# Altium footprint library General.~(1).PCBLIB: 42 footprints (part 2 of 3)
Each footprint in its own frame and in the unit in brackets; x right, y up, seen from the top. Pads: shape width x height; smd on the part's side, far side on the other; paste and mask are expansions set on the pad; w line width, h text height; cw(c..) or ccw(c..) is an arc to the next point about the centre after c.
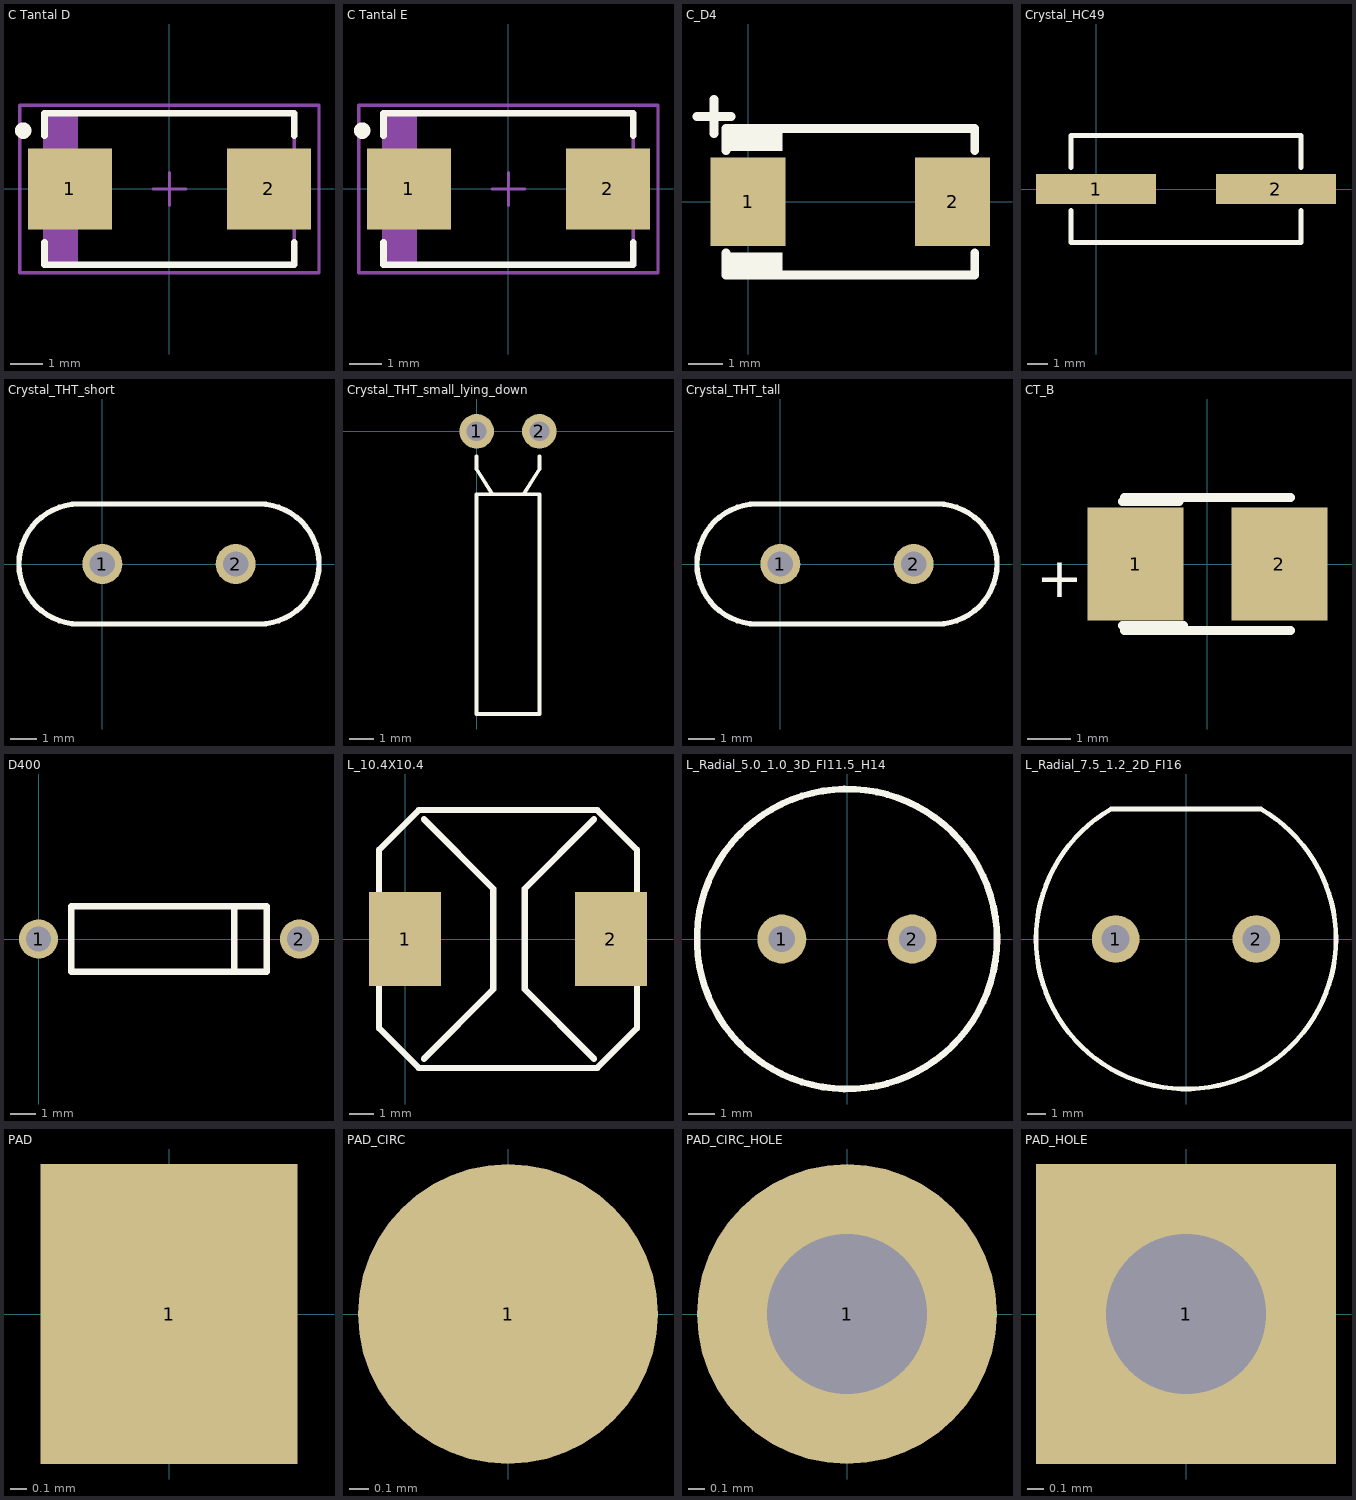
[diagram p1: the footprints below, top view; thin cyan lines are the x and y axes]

## C Tantal D [mm] "Molded Capacitor, 2-Leads, Body 7,3x4,3mm, IPC Medium Density"
height 3.1
pads (2):
  rect 2.55x2.45 smd: 1(-3.025,0) 2(3.025,0)
Top Overlay:
  circle w0.25: c-4.45,1.775 r0.125
  lines w0.2: -3.8,-1.625 -3.8,-2.3 3.8,-2.3 3.8,-1.625 ; -3.8,1.625 -3.8,2.3 3.8,2.3 3.8,1.625
Mechanical 13:
  rectangle: -3.8,-2.3 -2.778,2.3
  lines w0.1: -3.8,-2.3 3.8,-2.3 3.8,2.3 -3.8,2.3 -3.8,-2.3
Mechanical 15:
  lines w0.1: -0.5,0 0.5,0 ; 0,-0.5 0,0.5 ; -4.55,-2.55 4.55,-2.55 4.55,2.55 -4.55,2.55 -4.55,-2.55
3D body "User Library-cap_d.step": height 2.83, standoff 0.02, extent -3.647,-2.159 3.647,2.141

## C Tantal E [mm] "Molded Capacitor, 2-Leads, Body 7,3x4,3mm, IPC Medium Density"
height 4.3
pads (2):
  rect 2.55x2.45 smd: 1(-3.025,0) 2(3.025,0)
Top Overlay:
  circle w0.25: c-4.45,1.775 r0.125
  lines w0.2: -3.8,-1.625 -3.8,-2.3 3.8,-2.3 3.8,-1.625 ; -3.8,1.625 -3.8,2.3 3.8,2.3 3.8,1.625
Mechanical 13:
  rectangle: -3.8,-2.3 -2.778,2.3
  lines w0.1: -3.8,-2.3 3.8,-2.3 3.8,2.3 -3.8,2.3 -3.8,-2.3
Mechanical 15:
  lines w0.1: -0.5,0 0.5,0 ; 0,-0.5 0,0.5 ; -4.55,-2.55 4.55,-2.55 4.55,2.55 -4.55,2.55 -4.55,-2.55
3D body "User Library-cap_e.step": height 4.13, standoff 0.02, extent -3.647,-2.141 3.647,2.159

## C_D4 [mm]
pads (2):
  rect 2.2x2.6 smd: 1(0,0) 2(6,0)
Top Overlay:
  region: -0.625,1.5 1,1.5 1,2.25 -0.625,2.25
  region: -0.625,-2.25 1,-2.25 1,-1.5 -0.625,-1.5
  lines w0.254: -1.5,2.5 -0.5,2.5 ; -1,2 -1,3 ; -0.65,-1.5 -0.65,-2.15 6.65,-2.15 6.65,-1.5 ; -0.65,1.5 -0.65,2.15 6.65,2.15 6.65,1.5

## Crystal_HC49 [mm] "Crystall SMD short HC49"
height 4
pads (2):
  rect 6x1.5 smd: 1(0,0) 2(8.999,0)
Top Overlay:
  lines w0.254: -1.251,-1.079 -1.251,-2.667 10.25,-2.667 10.25,-1.079 ; -1.251,1.079 -1.251,2.667 10.25,2.667 10.25,1.079
3D body "User Library-hc49_cystal.step": height 5.08, standoff 0, extent -2.128,-2.413 11.272,2.487

## Crystal_THT_short [mil] "Crystal short THT"
height 157.48
pads (2):
  round 60 hole 38: 1(0,0) 2(200,0)
Top Overlay:
  lines w8: -35,-90 cw(c-35,0) -35,90 235,90 cw(c235,0) 235,-90 -35,-90
3D body "User Library-HP49US.step": height 138.4, standoff -156.88, extent -123.43,-90 323.43,93.07

## Crystal_THT_small_lying_down [mm]
pads (2):
  round 1.4 hole 0.8: 1(0,0) 2(2.54,0)
Top Overlay:
  lines w0.15: 0,-1.016 0,-1.524 0.635,-2.54 ; 1.905,-2.54 2.54,-1.524 2.54,-1.016 ; 0,-11.43 2.54,-11.43 2.54,-2.54 0,-2.54 0,-11.43

## Crystal_THT_tall [mil] "Crystal tall THT"
height 551.18
pads (2):
  round 60 hole 38: 1(0,0) 2(200,0)
Top Overlay:
  lines w8: -35,-90 cw(c-35,0) -35,90 235,90 cw(c235,0) 235,-90 -35,-90
3D body "User Library-Crystal_V2009.step": height 505.91, standoff -78.74, extent -112.6,-85 312.6,88.23

## CT_B [mm]
pads (2):
  rect 2.2x2.6 smd: 1(-1.651,0) 2(1.651,0)
Top Overlay:
  lines w0.203: -1.949,-1.414 -0.549,-1.414 ; -1.949,1.436 -0.649,1.436 ; -1.905,-1.524 1.905,-1.524 ; -1.905,1.524 1.905,1.524
  text "+" at -3.937,-0.762 h0.94

## D400 [mil]
pads (2):
  round 60 hole 38: 1(0,0) 2(400,0)
Top Overlay:
  lines w10: 300,-50 300,50 ; 50,-50 50,50 350,50 350,-50 50,-50

## L_10.4X10.4 [mm]
pads (2):
  rect 2.9x3.8 smd: 1(0,0) 2(8.3,0)
Top Overlay:
  lines w0.254: 0.762,-4.826 3.556,-2.032 3.556,2.032 0.762,4.826 ; 7.62,-4.826 4.826,-2.032 4.826,2.032 7.62,4.826 ; -1.05,-3.6 0.55,-5.2 7.75,-5.2 9.35,-3.6 9.35,3.6 7.75,5.2 0.55,5.2 -1.05,3.6 -1.05,-3.6
3D body "WE-PD_1030_Metal.stp": height 2.8, standoff 0.05, extent -0.838,-5 9.162,5

## L_Radial_5.0_1.0_3D_FI11.5_H14 [mil]
pads (2):
  round 74 hole 39.37: 1(-98.43,0) 2(98.43,0)
Top Overlay:
  circle w10: c0,0 r226.38
3D body "Coilcraft-DR0810-DEFAULT.step": height 453.36, standoff -176.56, extent -206.69,-208.39 206.69,205

## L_Radial_7.5_1.2_2D_FI16 [mm]
height 23
pads (2):
  round 2.54 hole 1.5: 1(-3.75,0) 2(3.75,0)
Top Overlay:
  lines w0.254: -4,6.928 ccw(c0,0) 4,6.928 -4,6.928
3D body: height 23, standoff 0, extent -8.001,-8.001 8.001,6.929

## PAD [mil]
pads (1):
  rect 60x70 smd: 1(0,0)

## PAD_CIRC [mil]
pads (1):
  round 60 smd: 1(0,0)

## PAD_CIRC_HOLE [mil]
pads (1):
  round 74 hole 39.4: 1(0,0)

## PAD_HOLE [mil]
pads (1):
  rect 74x74 hole 39.4: 1(0,0)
